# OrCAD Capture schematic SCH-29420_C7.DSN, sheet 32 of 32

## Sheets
32 P32_MISCELLANEOUS: size A2
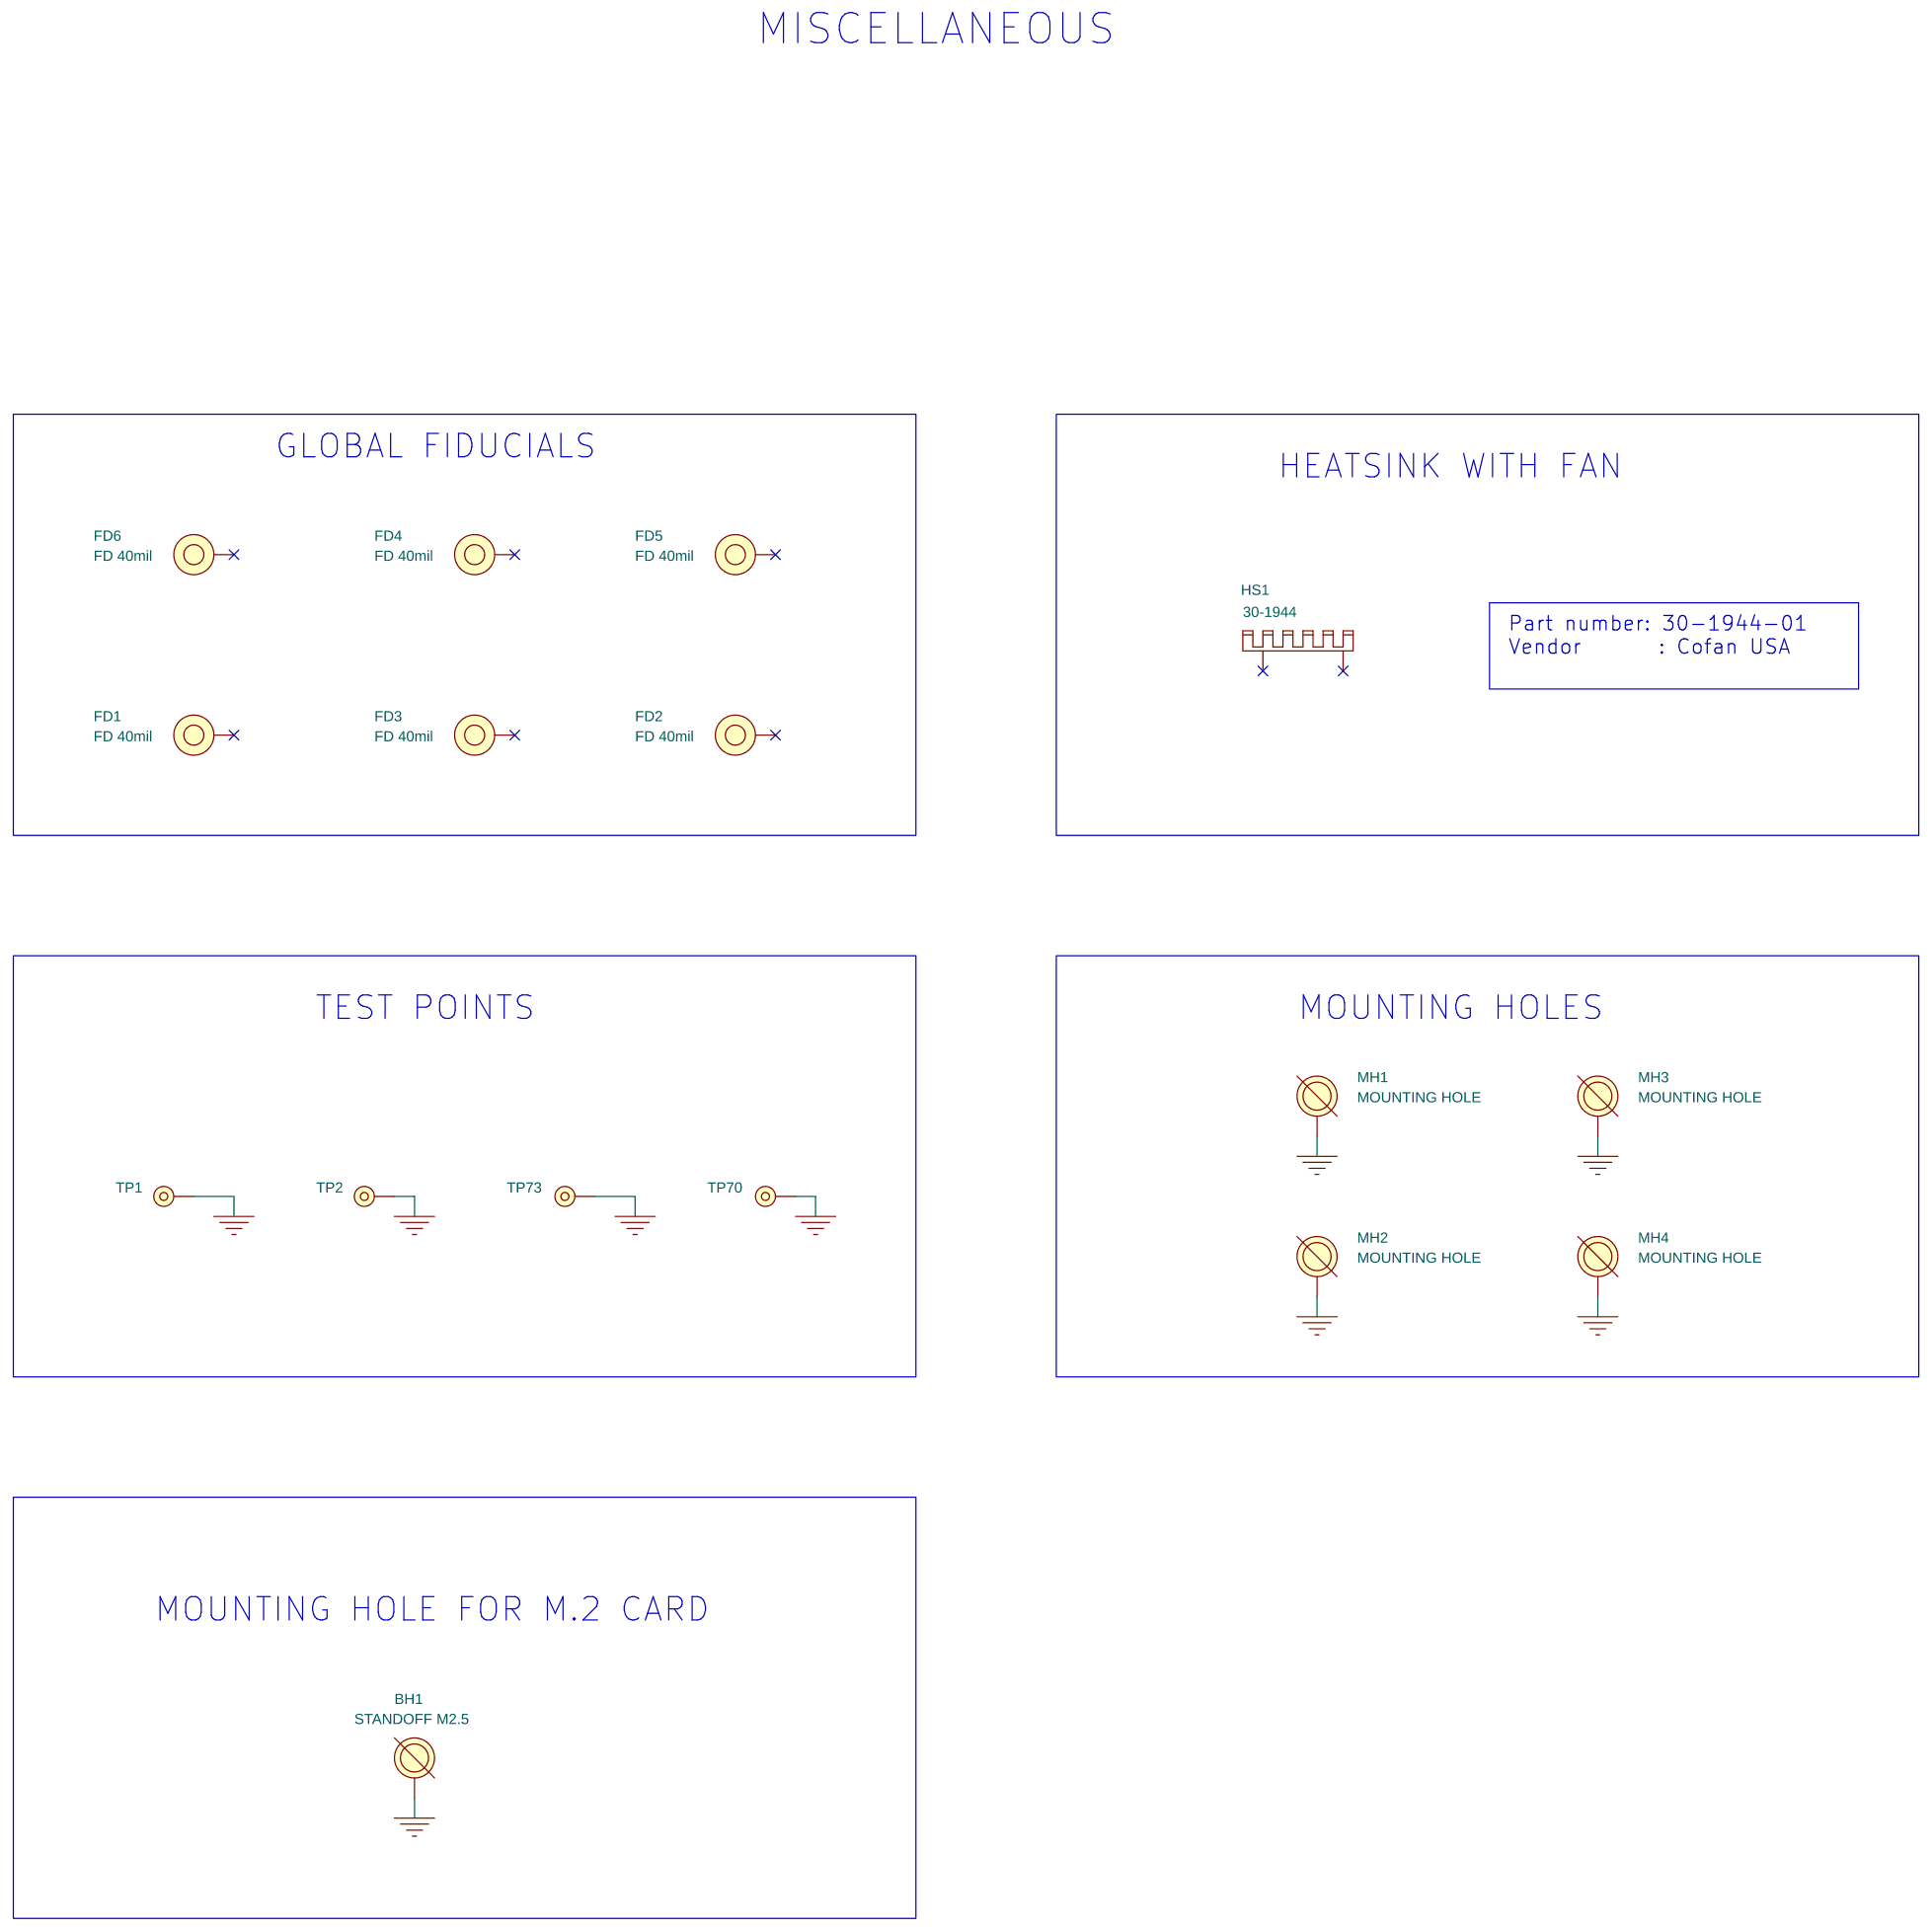
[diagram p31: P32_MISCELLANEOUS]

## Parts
BH1  STANDOFF M2.5  [standoff_circle_5p1-2p5mm]
FD1  FD 40mil  [FID_40MIL_SM080]
FD2  FD 40mil  [FID_40MIL_SM080]
FD3  FD 40mil  [FID_40MIL_SM080]
FD4  FD 40mil  [FID_40MIL_SM080]
FD5  FD 40mil  [FID_40MIL_SM080]
FD6  FD 40mil  [FID_40MIL_SM080]
HS1  30-1944  [fan_heatsink_s44p93]
MH1  MOUNTING HOLE  [mh_c197-126t]
MH2  MOUNTING HOLE  [mh_c197-126t]
MH3  MOUNTING HOLE  [mh_c197-126t]
MH4  MOUNTING HOLE  [mh_c197-126t]
TP1  TESTPOINT  [t_point0_7mm_r_1_2mm]
TP2  TESTPOINT  [t_point0_7mm_r_1_2mm]
TP70  TESTPOINT  [t_point0_7mm_r_1_2mm]
TP73  TESTPOINT  [t_point0_7mm_r_1_2mm]

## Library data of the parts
BH1 = MOUNT_HOLE: STANDOFF ROUND FEMALE 5.1-2.5 MM STEEL; AGILE_PN: 280-77180; CAD_APPROVED: Yes; EN: 601-1-00458; HEIGHT: 3.9 MM; MFG_NAME01: WURTH ELEKTRONIK EISOS GMBH & CO. KG; MFG_PN01: 9774025151R; ROHS: Yes
FD1-FD6 = FID-040: FIDUCIAL PLATED 40mil PAD 80mil SOLDERMASK SMD, NO PART TO ORDER; AGILE_PN: 510-77655; CAD_APPROVED: Yes; HEIGHT: 0.1MM; MFG_NAME01: NO PART TO ORDER; MFG_PN01: Local fiducial; ROHS: Yes
HS1 = HEATSINK_2P: HEATSINK W/ 12V FAN  TH; AGILE_PN: 801-76286; CAD_APPROVED: Yes; EN: 203-1-00086; HEIGHT: 11.45MM; MFG_NAME01: COFAN USA; MFG_PN01: 30-1944 Rev 01; ROHS: Yes
MH1-MH4 = MOUNT_HOLE: MOUNTING HOLE DRILL 126 PAD 197 PLATED TH NO PART TO ORDER; AGILE_PN: 280-77075; CAD_APPROVED: Yes; HEIGHT: 0.127MM; MFG_NAME01: N/A; MFG_PN01: N/A; ROHS: Yes
TP1 TP2 TP70 TP73 = T_POINT_TH: TEST POINT PAD 50 DRILL 28 DIAM TH, NO PART TO ORDER; AGILE_PN: 210-80291; CAD_APPROVED: Yes; HEIGHT: 0.1 MM; MFG_NAME01: NOTACOMPONENT; MFG_PN01: NOTACOMPONENT; ROHS: Yes

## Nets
GND: BH1.1 MH1.1 MH2.1 MH3.1 MH4.1 TP1.1(TP) TP2.1(TP) TP70.1(TP) TP73.1(TP) ; also on sheet 2 5 6 10 11 12 13 14 16 17 18 19 20 21 22 23 24 25 26 27 28 29 30 31

Not connected (* = marked no-connect by the designer): FD1 1(NC)*; FD2 1(NC)*; FD3 1(NC)*; FD4 1(NC)*; FD5 1(NC)*; FD6 1(NC)*; HS1 1* 2*

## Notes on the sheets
sheet 32
- MISCELLANEOUS
- GLOBAL FIDUCIALS
- HEATSINK WITH FAN
- Part number: 30-1944-01
  Vendor       : Cofan USA
- TEST POINTS
- MOUNTING HOLES
- MOUNTING HOLE FOR M.2 CARD
